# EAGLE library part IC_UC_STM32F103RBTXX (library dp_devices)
32-bit ARM-based MCU with 64 or 128KB Flash
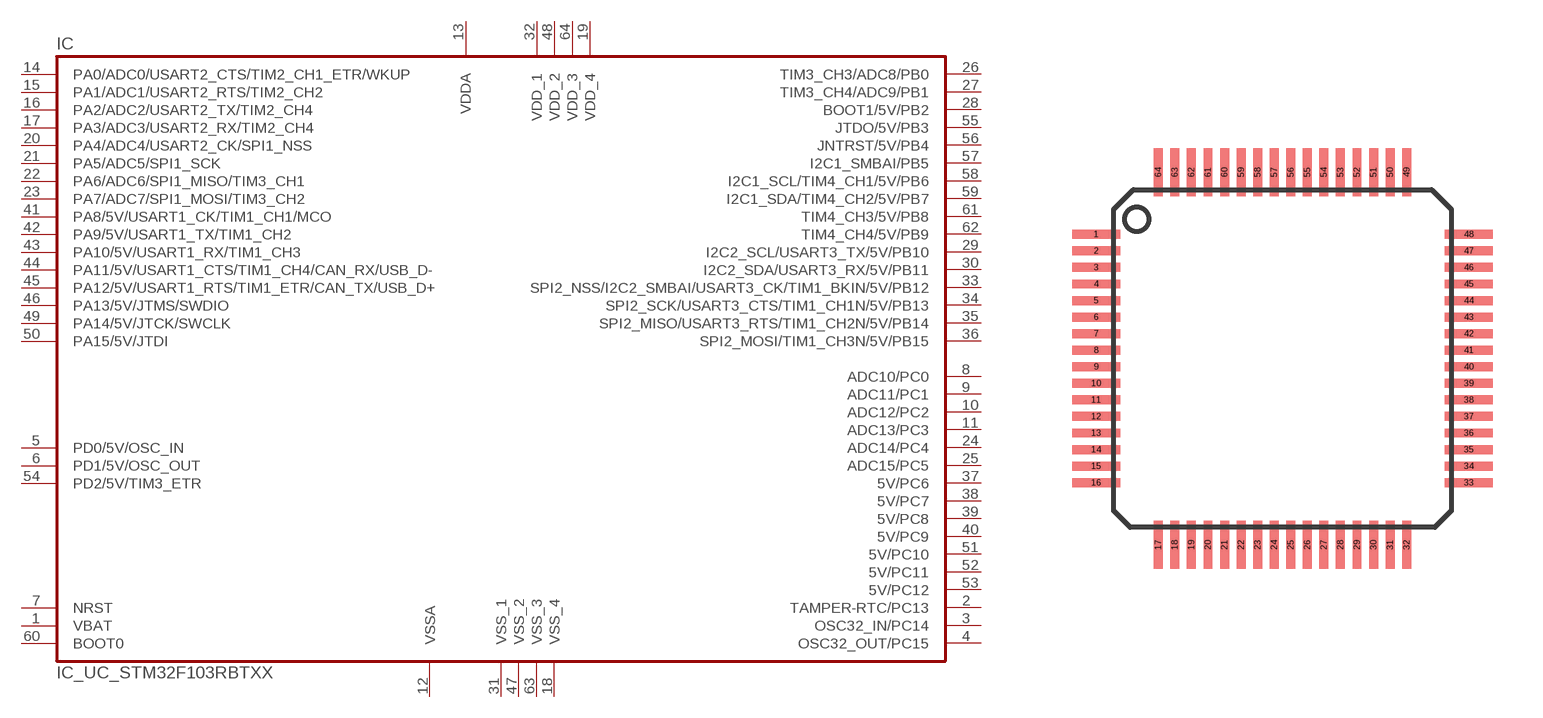
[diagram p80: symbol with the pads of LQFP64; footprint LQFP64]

Designator prefix IC

## IC_UC_STM32F103RBTXX-LQFP64  [LQFP64]
1  VBAT  pwr
2  TAMPER-RTC/PC13
3  OSC32_IN/PC14
4  OSC32_OUT/PC15
5  PD0/5V/OSC_IN  in
6  PD1/5V/OSC_OUT  out
7  NRST
8  ADC10/PC0
9  ADC11/PC1
10  ADC12/PC2
11  ADC13/PC3
12  VSSA  sup
13  VDDA  pwr
14  PA0/ADC0/USART2_CTS/TIM2_CH1_ETR/WKUP
15  PA1/ADC1/USART2_RTS/TIM2_CH2
16  PA2/ADC2/USART2_TX/TIM2_CH4
17  PA3/ADC3/USART2_RX/TIM2_CH4
18  VSS_4  sup
19  VDD_4  pwr
20  PA4/ADC4/USART2_CK/SPI1_NSS
21  PA5/ADC5/SPI1_SCK
22  PA6/ADC6/SPI1_MISO/TIM3_CH1
23  PA7/ADC7/SPI1_MOSI/TIM3_CH2
24  ADC14/PC4
25  ADC15/PC5
26  TIM3_CH3/ADC8/PB0
27  TIM3_CH4/ADC9/PB1
28  BOOT1/5V/PB2
29  I2C2_SCL/USART3_TX/5V/PB10
30  I2C2_SDA/USART3_RX/5V/PB11
31  VSS_1  sup
32  VDD_1  pwr
33  SPI2_NSS/I2C2_SMBAI/USART3_CK/TIM1_BKIN/5V/PB12
34  SPI2_SCK/USART3_CTS/TIM1_CH1N/5V/PB13
35  SPI2_MISO/USART3_RTS/TIM1_CH2N/5V/PB14
36  SPI2_MOSI/TIM1_CH3N/5V/PB15
37  5V/PC6
38  5V/PC7
39  5V/PC8
40  5V/PC9
41  PA8/5V/USART1_CK/TIM1_CH1/MCO
42  PA9/5V/USART1_TX/TIM1_CH2
43  PA10/5V/USART1_RX/TIM1_CH3
44  PA11/5V/USART1_CTS/TIM1_CH4/CAN_RX/USB_D-
45  PA12/5V/USART1_RTS/TIM1_ETR/CAN_TX/USB_D+
46  PA13/5V/JTMS/SWDIO
47  VSS_2  sup
48  VDD_2  pwr
49  PA14/5V/JTCK/SWCLK
50  PA15/5V/JTDI
51  5V/PC10
52  5V/PC11
53  5V/PC12
54  PD2/5V/TIM3_ETR
55  JTDO/5V/PB3
56  JNTRST/5V/PB4
57  I2C1_SMBAI/PB5
58  I2C1_SCL/TIM4_CH1/5V/PB6
59  I2C1_SDA/TIM4_CH2/5V/PB7
60  BOOT0  in
61  TIM4_CH3/5V/PB8
62  TIM4_CH4/5V/PB9
63  VSS_3  sup
64  VDD_3  pwr

## Footprint LQFP64 (pad centres in mm)
LQFP64 Richard Myrick T. Arellaga March2010
smd 1.45 x 0.27: 1 -5.625,3.75; 2 -5.625,3.25; 3 -5.625,2.75; 4 -5.625,2.25; 5 -5.625,1.75; 6 -5.625,1.25; 7 -5.625,0.75; 8 -5.625,0.25; 9 -5.625,-0.25; 10 -5.625,-0.75; 11 -5.625,-1.25; 12 -5.625,-1.75; 13 -5.625,-2.25; 14 -5.625,-2.75; 15 -5.625,-3.25; 16 -5.625,-3.75; 33 5.625,-3.75; 34 5.625,-3.25; 35 5.625,-2.75; 36 5.625,-2.25; 37 5.625,-1.75; 38 5.625,-1.25; 39 5.625,-0.75; 40 5.625,-0.25; 41 5.625,0.25; 42 5.625,0.75; 43 5.625,1.25; 44 5.625,1.75; 45 5.625,2.25; 46 5.625,2.75; 47 5.625,3.25; 48 5.625,3.75
smd 0.27 x 1.45: 17 -3.75,-5.625; 18 -3.25,-5.625; 19 -2.75,-5.625; 20 -2.25,-5.625; 21 -1.75,-5.625; 22 -1.25,-5.625; 23 -0.75,-5.625; 24 -0.25,-5.625; 25 0.25,-5.625; 26 0.75,-5.625; 27 1.25,-5.625; 28 1.75,-5.625; 29 2.25,-5.625; 30 2.75,-5.625; 31 3.25,-5.625; 32 3.75,-5.625; 49 3.75,5.625; 50 3.25,5.625; 51 2.75,5.625; 52 2.25,5.625; 53 1.75,5.625; 54 1.25,5.625; 55 0.75,5.625; 56 0.25,5.625; 57 -0.25,5.625; 58 -0.75,5.625; 59 -1.25,5.625; 60 -1.75,5.625; 61 -2.25,5.625; 62 -2.75,5.625; 63 -3.25,5.625; 64 -3.75,5.625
